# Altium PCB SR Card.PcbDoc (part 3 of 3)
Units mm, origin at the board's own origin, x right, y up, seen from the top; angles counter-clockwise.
Board outline 110.01 x 84.94 mm, 10 copper layers (Top Layer, Layer 2, Layer 3, Layer 4, Layer 5, Layer 6, Layer 7, Layer 8, Layer 9, Bottom Layer), stack 2.452 mm thick; 165 components, 84 nets, 582 pads, 1965 vias.
Unrouted connection lines stored in the file: 24.
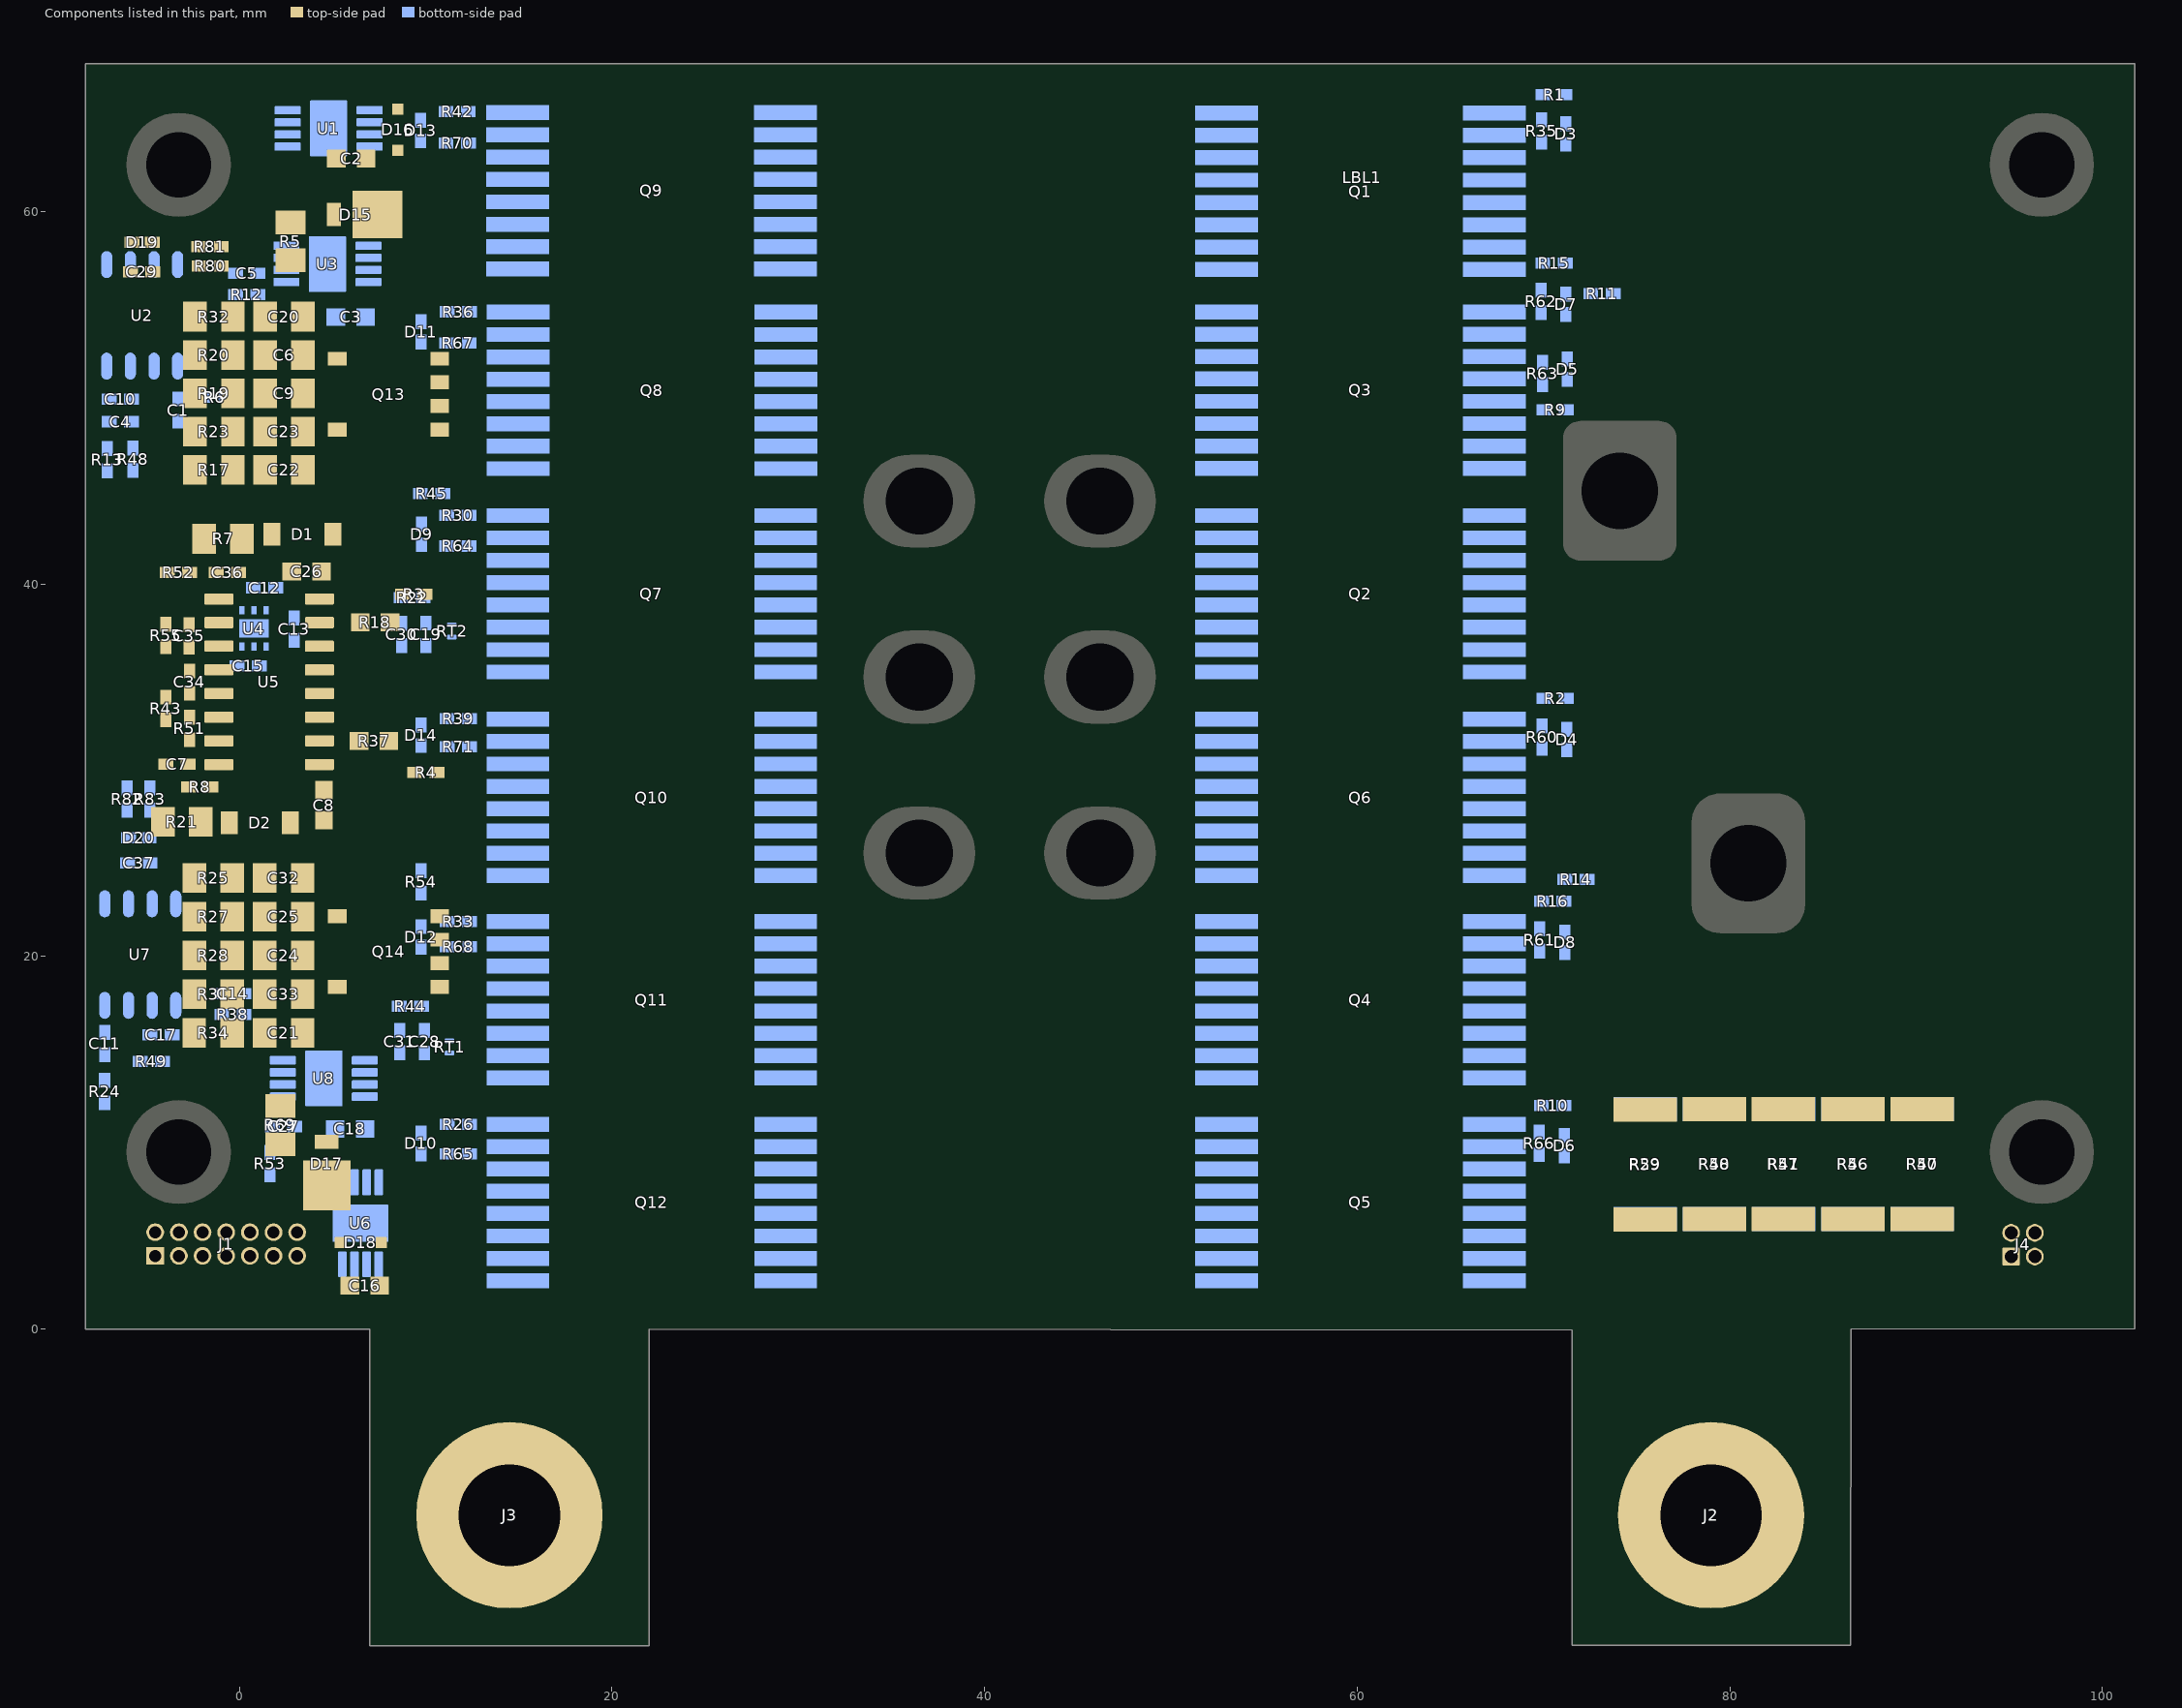
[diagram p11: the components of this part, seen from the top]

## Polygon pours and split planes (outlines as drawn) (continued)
NetC2_1 on Bottom Layer "BOTTOM_LAYER_NONET_P365" (solid, pour order 365): 22 vertices, not listed, extent 1.774,61.651 7.887,63.7
"SR1 LO" on Bottom Layer "BOTTOM_LAYER_SR1_LO_P364" (solid, pour order 364): 6.219,56.632 6.153,56.698 6.153,57.587 6.274,57.708 7.654,57.708 7.805,57.558 7.805,56.764 7.669,56.628 7.409,56.628
DGND on Bottom Layer "BOTTOM_LAYER_DGND_P363" (solid, pour order 363): 29 vertices, not listed, extent -1.053,53.832 7.809,59.908
"SR1 HO" on Bottom Layer "BOTTOM_LAYER_SR1_HO_P353" (solid, pour order 353): 6.297,63.909 6.253,63.953 6.253,64.924 6.33,65.002 7.692,65.002 7.789,64.904 7.789,63.995 7.701,63.908
VSEC+ on Bottom Layer "BOTTOM_LAYER_VSEC+_P352" (solid, pour order 352): 17 vertices, not listed, extent 1.746,62.576 8.446,66.796
DGND on Bottom Layer "Bottom Layer-DGND" (solid, pour order 346): 21 vertices, not listed, extent 7.014,-16.999 21.996,66.742
VBIAS on Bottom Layer "BOTTOM_LAYER_VBIAS_P317" (solid, pour order 317): 93.908,0.927 93.908,7.879 93.095,8.693 71.987,8.693 71.518,6.854 71.518,-16.978 86.463,-16.978 86.463,0.058 86.5,0.022 93.004,0.022
VSR on Bottom Layer "BOTTOM_LAYER_VSR_P308" (solid, remove dead copper, pour order 308): 17 vertices, not listed, extent 60.72,1.857 101.745,67.544
VOUT on Bottom Layer "BOTTOM_LAYER_VOUT_P264" (solid, remove dead copper, pour order 264): 94.2,8.978 97.219,5.96 97.219,1.284 98.086,0.417 100.438,0.417 101.745,1.724 101.745,27.694 100.104,29.336 77.048,29.336 72.036,9.026
VSEC- on Bottom Layer "BOTTOM_LAYER_VSEC-_P239" (solid, pour order 239): 20 vertices, not listed, extent 22.617,1.788 59.33,33.345
VSEC+ on Bottom Layer "BOTTOM_LAYER_VSEC+_P022" (solid, remove dead copper, pour order 22): 19 vertices, not listed, extent 22.583,22.49 59.637,65.946
DGND on Layer 9 "LAYER_9_DGND_P229" (solid, pour order 229): 20 vertices, not listed, extent -8.263,-16.999 101.745,67.936
VSEC- on Layer 9 "LAYER_9_VSEC-_P388" (solid, pour order 388): 23.902,1.693 31.778,1.693 31.778,33.795 23.902,33.795
VSEC+ on Layer 9 "LAYER_9_VSEC+_P311" (solid, pour order 311): 23.888,34.258 31.764,34.258 31.764,66.36 23.888,66.36
VBIAS on Layer 9 "LAYER_9_VBIAS_P341" (solid, pour order 341): 90.97,0.022 93.004,0.022 93.908,0.927 93.908,7.879 93.095,8.693 71.987,8.693 71.518,6.854 71.518,-16.978 86.463,-16.978 86.463,0.058 86.5,0.022
VOUT on Layer 9 "LAYER_9_VOUT_P340" (solid, remove dead copper, pour order 340): 94.136,8.979 94.186,8.979 97.2,5.964 97.2,1.303 98.108,0.395 100.721,0.395 101.745,1.419 101.745,28.007 100.416,29.336 77.048,29.336 72.036,9.026
VSR on Layer 9 "LAYER_9_VSR_P316" (solid, pour order 316): 78.304,31.96 99.913,31.96 99.913,67.043 78.304,67.043
VSEC+ on Layer 9 "LAYER_9_VSEC+_P315" (solid, pour order 315): 57.142,0.357 57.142,66.449 56.645,66.946 49.959,66.946 49.176,66.163 49.266,66.073 49.266,2.767 49.236,2.737 49.266,2.707 49.266,0.598
VSR on Layer 9 "LAYER_9_VSR_P313" (solid, pour order 313): 69.802,0.334 69.802,66.426 69.305,66.924 62.619,66.924 61.836,66.141 61.926,66.05 61.926,2.744 61.896,2.714 61.926,2.684 61.926,0.576
VSEC- on Layer 9 "LAYER_9_VSEC-_P312" (solid, pour order 312): 57.142,0.357 57.142,66.449 56.645,66.946 49.959,66.946 49.176,66.163 49.266,66.073 49.266,2.767 49.236,2.737 49.266,2.707 49.266,0.598
AGND on Layer 2 "LAYER_2_AGND_P344" (solid, remove dead copper, pour order 344): 18 vertices, not listed, extent -8.259,-0.029 8.344,41.938
DGND on Layer 2 "LAYER_2_DGND_P282" (solid, remove dead copper, pour order 282): 20 vertices, not listed, extent -8.263,0.78 21.995,67.359
VBIAS on Layer 2 "LAYER_2_VBIAS_P337" (solid, pour order 337): 93.893,3.56 93.893,7.895 93.095,8.693 71.987,8.693 71.518,6.854 71.518,-16.978 86.463,-16.955 86.463,0.058 86.5,0.022 92.346,0.022 93.893,1.569
VOUT on Layer 2 "LAYER_2_VOUT_P336" (solid, remove dead copper, pour order 336): 94.009,8.979 97.206,5.782 97.206,1.25 98.06,0.395 100.746,0.395 101.745,1.394 101.745,27.898 100.307,29.336 77.048,29.336 72.036,9.026
VSR on Layer 2 "LAYER_2_VSR_P300" (solid, remove dead copper, pour order 300): 20 vertices, not listed, extent 60.72,1.857 101.745,67.544
VSEC- on Layer 2 "LAYER_2_VSEC-_P287" (solid, pour order 287): 34 vertices, not listed, extent 71.708,10.877 75.431,33.607
VSEC+ on Layer 2 "LAYER_2_VSEC+_P286" (solid, pour order 286): 30 vertices, not listed, extent 71.814,49.781 75.316,65.928
DGND on Layer 2 "LAYER_2_DGND_P283" (solid, pour order 283): 7,-17.004 7,-0.008 7.007,-0.001 21.986,-0.001 21.996,-0.01 21.996,-16.998
VSEC+ on Layer 2 "LAYER_2_VSEC+_P255" (solid, pour order 255): 59.382,65.951 59.637,65.695 59.637,2.439 58.987,1.788 23.196,1.788 22.604,2.38 22.604,65.461 23.093,65.951
VSEC- on Layer 2 "LAYER_2_VSEC-_P254" (solid, pour order 254): 40.395,46.429 45.236,41.588 49.521,41.588 51.629,39.48 59.637,39.48 59.637,2.439 58.987,1.788 23.196,1.788 22.604,2.38 22.604,46.429
DGND on Layer 5 "LAYER_5_DGND_P304" (solid, remove dead copper, pour order 304): 6.974,-16.999 22.001,-16.999 22.001,67.581 21.686,67.895 -8.268,67.895 -8.268,1.978 -6.395,0.105 6.974,0.105
VBIAS on Layer 5 "LAYER_5_VBIAS_P331" (solid, pour order 331): 93.908,1.555 93.908,7.879 93.095,8.693 71.987,8.693 71.518,6.854 71.518,-16.978 86.463,-16.978 86.463,0.058 86.5,0.022 92.375,0.022
VOUT on Layer 5 "LAYER_5_VOUT_P330" (solid, remove dead copper, pour order 330): 94.275,8.978 94.275,8.632 97.239,5.668 97.239,1.217 98.06,0.395 100.485,0.395 101.745,1.655 101.745,28.104 100.513,29.336 77.048,29.336 72.036,9.026
VSR on Layer 5 "LAYER_5_VSR_P294" (solid, remove dead copper, pour order 294): 100.822,29.554 101.745,30.477 101.745,66.054 100.255,67.544 60.72,67.544 60.72,1.857 71.315,1.857 71.315,6.854 76.847,29.373 77.05,29.538
VSEC- on Layer 5 "LAYER_5_VSEC-_P259" (solid, pour order 259): 59.386,65.946 59.637,65.695 59.637,2.439 58.987,1.788 23.196,1.788 22.604,2.38 22.604,65.461 23.089,65.946
VSEC+ on Layer 5 "LAYER_5_VSEC+_P258" (solid, pour order 258): 41.846,22.016 36.568,27.294 22.604,27.294 22.604,65.461 23.089,65.946 59.386,65.946 59.637,65.695 59.637,22.016
DGND on Layer 3 "LAYER_3_DGND_P386" (solid, remove dead copper, pour order 386): 6.974,-16.999 22.001,-16.999 22.001,67.581 21.686,67.895 -8.268,67.895 -8.268,1.978 -6.395,0.105 6.974,0.105
"SR1 LO" on Layer 3 "LAYER_3_SR1_LO_P280" (solid, pour order 280): 50 vertices, not listed, extent 6.486,42.661 11.667,65.156
VBIAS on Layer 3 "LAYER_3_VBIAS_P351" (solid, pour order 351): 71.518,2.551 75.738,6.77 75.738,8.693 93.095,8.693 93.894,7.894 93.894,1.57 92.346,0.022 86.5,0.022 86.463,0.058 86.463,-16.955 71.518,-16.978
VOUT on Layer 3 "LAYER_3_VOUT_P350" (solid, remove dead copper, pour order 350): 95.16,9.026 95.16,7.829 97.242,5.748 97.242,1.214 98.06,0.395 100.439,0.395 101.414,1.369 101.414,28.204 100.281,29.336 77.048,29.336 75.738,24.027 75.738,9.026
VSR on Layer 3 "LAYER_3_NONET_P349" (solid, pour order 349): 24 vertices, not listed, extent 60.72,2.048 101.745,67.544
"SR1 HO" on Layer 3 "LAYER_3_SR1_HO_P348" (solid, pour order 348): 32 vertices, not listed, extent 70.813,50.099 75.316,65.988
"SR2 HO" on Layer 3 "LAYER_3_SR2_HO_P347" (solid, pour order 347): 34 vertices, not listed, extent 70.725,10.594 75.431,33.673
"SR2 LO" on Layer 3 "LAYER_3_SR2_LO_P281" (solid, pour order 281): 56 vertices, not listed, extent 6.35,9.871 12.241,32.594
VSEC- on Layer 3 "LAYER_3_VSEC-_P261" (solid, pour order 261): 59.386,65.946 59.637,65.695 59.637,2.439 58.987,1.788 23.196,1.788 22.604,2.38 22.604,65.461 23.089,65.946
VSEC+ on Layer 3 "LAYER_3_VSEC+_P260" (solid, pour order 260): 41.846,22.016 36.568,27.294 22.604,27.294 22.604,65.461 23.089,65.946 59.386,65.946 59.637,65.695 59.637,22.016

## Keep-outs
Keep-Out Layer:
  lines w0.254: 6.669,0.025 -8.29,0 -8.293,67.942 101.75,67.94 101.75,0 86.886,-0.02 ; 22.349,-0.011 71.206,-0.072
  text ".Layer_Name" at 4.656,-21.806 h0.6

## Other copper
Top Layer:
  rectangle net NetD1_2: -0.337,41.958 2.132,43.262
  rectangle net NetD2_2: -2.544,26.528 -0.075,27.833
  text ".Layer_Name" at 4.656,-21.806 h0.6
Layer 3:
  pour cut-out: 1.331,37.219 cw(c1.331,37.848) 0.702,37.848 cw(c1.331,37.848) 1.331,38.476 cw(c1.331,37.848) 1.959,37.848 cw(c1.331,37.848)
  pour cut-out: 0.702,37.282 cw(c0.702,37.91) 0.074,37.91 cw(c0.702,37.91) 0.702,38.539 cw(c0.702,37.91) 1.331,37.91 cw(c0.702,37.91)
  pour cut-out: 1.331,37.219 cw(c1.331,37.848) 0.702,37.848 cw(c1.331,37.848) 1.331,38.476 cw(c1.331,37.848) 1.959,37.848 cw(c1.331,37.848)
  pour cut-out: 8.274,34.085 cw(c8.274,34.713) 7.646,34.713 cw(c8.274,34.713) 8.274,35.341 cw(c8.274,34.713) 8.903,34.713 cw(c8.274,34.713)
  region net VSEC+: 3.932,65.77 3.932,63.171 4.119,62.984 5.536,62.984 5.627,63.076 5.627,65.821 5.448,66 4.163,66
  region net VSEC-: 6.314,4.847 6.172,4.989 6.172,6.314 6.345,6.488 7.907,6.488 8.005,6.389 8.005,4.954 7.899,4.847
  region net DGND: -2.595,17.497 -2.415,17.676 -1.901,17.676 -1.746,17.522 -1.746,15.194 -1.952,14.988 -2.423,14.988 -2.595,15.16
  region net DGND: -2.443,19.617 -1.92,19.617 -1.738,19.8 -1.738,24.932 -1.9,25.094 -2.369,25.094 -2.591,24.872 -2.591,19.765
  region net DGND: -3.666,47.665 -3.448,47.883 -2.889,47.883 -2.571,48.201 -2.571,48.597 -2.335,48.834 -1.861,48.834 -1.707,48.679 -1.707,46.339 -1.969,46.077 -3.419,46.077 -3.666,46.324
  region net DGND: -3.427,52.583 -3.601,52.757 -3.601,54.163 -3.341,54.422 -1.957,54.422 -1.729,54.195 -1.729,50.985 -1.95,50.764 -2.321,50.764 -2.561,51.004 -2.561,52.284 -2.86,52.583
  region net NetC6_2: -0.645,54.608 -0.463,54.789 0.743,54.789 1.055,54.477 1.055,53.111 1.71,52.456 1.71,46.048 1.493,45.831 -0.47,45.831 -0.645,46.006
  region net NetC21_2: 1.464,19.681 -0.499,19.681 -0.692,19.874 -0.692,24.405 -0.479,24.618 1.457,24.618 1.681,24.394 1.681,19.898
  region net NetC6_1: 7.098,48.584 4.996,48.584 4.638,48.941 4.638,51.473 5.08,51.914 7.039,51.914 7.479,51.474 7.479,48.965
  region net NetC21_1: 5.395,18.683 5.556,18.844 5.556,22.255 6.064,22.763 7.132,22.763 7.498,23.093 7.498,23.667 7.118,24.047 5.134,24.047 4.658,23.571 4.658,18.912 4.886,18.683
  pour cut-out: -2.49,50.375 -2.955,50.84 -2.955,51.872 -3.195,52.112 -3.734,52.112 -4.011,52.378 -4.011,54.461 -3.568,54.903 -1.781,54.903 -1.417,54.539 -1.417,50.609 -1.65,50.375
  pour cut-out: -3.022,19.579 -2.63,19.187 -1.74,19.187 -1.345,19.582 -1.345,25.237 -1.705,25.598 -2.678,25.598 -3.022,25.254
  pour cut-out: -3.022,14.992 -2.464,14.434 -1.822,14.434 -1.345,14.911 -1.345,17.813 -1.705,18.173 -2.678,18.173 -3.022,17.829
  pour cut-out: -4.011,45.921 -3.765,45.675 -1.682,45.675 -1.417,45.929 -1.417,48.971 -1.68,49.233 -2.569,49.233 -2.905,48.897 -2.905,48.418 -3.154,48.17 -3.767,48.17 -4.012,47.925 -4.011,47.792
Layer 5:
  pour cut-out: -4.422,38.529 cw(c-4.422,39.157) -5.05,39.157 cw(c-4.422,39.157) -4.422,39.785 cw(c-4.422,39.157) -3.794,39.157 cw(c-4.422,39.157)
  pour cut-out: 8.274,34.085 cw(c8.274,34.713) 7.646,34.713 cw(c8.274,34.713) 8.274,35.341 cw(c8.274,34.713) 8.903,34.713 cw(c8.274,34.713)
  pour cut-out: 0.702,37.219 cw(c0.702,37.848) 0.074,37.848 cw(c0.702,37.848) 0.702,38.476 cw(c0.702,37.848) 1.331,37.848 cw(c0.702,37.848)
  pour cut-out: 1.331,37.219 cw(c1.331,37.848) 0.702,37.848 cw(c1.331,37.848) 1.331,38.476 cw(c1.331,37.848) 1.959,37.848 cw(c1.331,37.848)
  pour cut-out: -2.752,3.103 -2.618,2.968 -1.38,2.968 -1.21,3.138 -1.21,5.784 -1.385,5.958 -2.559,5.958 -2.752,5.765
  region net DGND: -3.427,52.583 -3.601,52.757 -3.601,54.163 -3.341,54.422 -1.957,54.422 -1.729,54.195 -1.729,50.985 -1.95,50.764 -2.321,50.764 -2.561,51.004 -2.561,52.284 -2.86,52.583
  region net DGND: -3.666,47.665 -3.448,47.883 -2.889,47.883 -2.571,48.201 -2.571,48.597 -2.335,48.834 -1.861,48.834 -1.707,48.679 -1.707,46.339 -1.969,46.077 -3.419,46.077 -3.666,46.324
  region net DGND: -2.443,19.617 -1.92,19.617 -1.738,19.8 -1.738,24.932 -1.9,25.094 -2.369,25.094 -2.591,24.872 -2.591,19.765
  region net DGND: -2.595,17.497 -2.415,17.676 -1.901,17.676 -1.746,17.522 -1.746,15.194 -1.952,14.988 -2.423,14.988 -2.595,15.16
  region net VSEC-: 6.314,4.847 6.172,4.989 6.172,6.314 6.345,6.488 7.907,6.488 8.005,6.389 8.005,4.954 7.899,4.847
  region net VSEC+: 3.932,65.77 3.932,63.171 4.119,62.984 5.536,62.984 5.627,63.076 5.627,65.821 5.448,66 4.163,66
  region net NetC6_2: -0.645,54.608 -0.463,54.789 0.743,54.789 1.055,54.477 1.055,53.111 1.71,52.456 1.71,46.048 1.493,45.831 -0.47,45.831 -0.645,46.006
  region net NetC21_2: 1.464,19.681 -0.499,19.681 -0.692,19.874 -0.692,24.405 -0.479,24.618 1.457,24.618 1.681,24.394 1.681,19.898
  region net NetC21_1: 7.117,18.554 5.015,18.554 4.658,18.912 4.658,23.571 5.134,24.047 7.058,24.047 7.498,23.607 7.498,18.935
  region net NetC6_1: 7.098,48.584 4.996,48.584 4.638,48.941 4.638,51.473 5.08,51.914 7.039,51.914 7.479,51.474 7.479,48.965
  pour cut-out: -2.49,50.375 -2.955,50.84 -2.955,51.872 -3.195,52.112 -3.734,52.112 -4.011,52.378 -4.011,54.461 -3.568,54.903 -1.781,54.903 -1.417,54.539 -1.417,50.609 -1.65,50.375
  pour cut-out: -3.022,19.579 -2.63,19.187 -1.74,19.187 -1.345,19.582 -1.345,25.237 -1.705,25.598 -2.678,25.598 -3.022,25.254
  pour cut-out: -3.022,14.992 -2.464,14.434 -1.822,14.434 -1.345,14.911 -1.345,17.813 -1.705,18.173 -2.678,18.173 -3.022,17.829
  pour cut-out: -4.011,45.921 -3.765,45.675 -1.682,45.675 -1.417,45.929 -1.417,48.971 -1.68,49.233 -2.569,49.233 -2.905,48.897 -2.905,48.294 -3.03,48.17 -3.767,48.17 -4.012,47.925 -4.011,47.792
Layer 6:
  pour cut-out: -4.422,38.529 cw(c-4.422,39.157) -5.05,39.157 cw(c-4.422,39.157) -4.422,39.785 cw(c-4.422,39.157) -3.794,39.157 cw(c-4.422,39.157)
  pour cut-out: 0.707,37.214 cw(c0.707,37.843) 0.079,37.843 cw(c0.707,37.843) 0.707,38.471 cw(c0.707,37.843) 1.336,37.843 cw(c0.707,37.843)
  pour cut-out: 1.331,37.219 cw(c1.331,37.848) 0.702,37.848 cw(c1.331,37.848) 1.331,38.476 cw(c1.331,37.848) 1.959,37.848 cw(c1.331,37.848)
  pour cut-out: 8.274,34.085 cw(c8.274,34.713) 7.646,34.713 cw(c8.274,34.713) 8.274,35.341 cw(c8.274,34.713) 8.903,34.713 cw(c8.274,34.713)
  pour cut-out: -2.752,3.05 -1.21,3.05 -1.21,5.784 -1.385,5.958 -2.559,5.958 -2.752,5.765
  region net DGND: -3.427,52.583 -3.601,52.757 -3.601,54.163 -3.341,54.422 -1.957,54.422 -1.729,54.195 -1.729,50.985 -1.95,50.764 -2.321,50.764 -2.561,51.004 -2.561,52.284 -2.86,52.583
  region net DGND: -3.666,47.665 -3.448,47.883 -2.889,47.883 -2.571,48.201 -2.571,48.597 -2.335,48.834 -1.861,48.834 -1.707,48.679 -1.707,46.339 -1.969,46.077 -3.419,46.077 -3.666,46.324
  region net DGND: -2.443,19.617 -1.92,19.617 -1.738,19.8 -1.738,24.932 -1.9,25.094 -2.369,25.094 -2.591,24.872 -2.591,19.765
  region net DGND: -2.595,17.497 -2.415,17.676 -1.901,17.676 -1.746,17.522 -1.746,15.194 -1.952,14.988 -2.423,14.988 -2.595,15.16
  region net VSEC-: 6.314,4.847 6.172,4.989 6.172,6.314 6.345,6.488 7.907,6.488 8.005,6.389 8.005,4.954 7.899,4.847
  region net VSEC+: 3.932,65.77 3.932,63.171 4.119,62.984 5.536,62.984 5.627,63.076 5.627,65.821 5.448,66 4.163,66
  region net NetC6_2: -0.645,54.608 -0.463,54.789 0.743,54.789 1.055,54.477 1.055,53.111 1.71,52.456 1.71,46.048 1.493,45.831 -0.47,45.831 -0.645,46.006
  region net NetC21_2: 1.464,19.681 -0.499,19.681 -0.692,19.874 -0.692,24.405 -0.479,24.618 1.457,24.618 1.681,24.394 1.681,19.898
  region net NetC21_1: 7.117,18.554 5.015,18.554 4.658,18.912 4.658,23.571 5.134,24.047 7.058,24.047 7.498,23.607 7.498,18.935
  region net NetC6_1: 7.098,48.584 4.996,48.584 4.638,48.941 4.638,51.473 5.08,51.914 7.039,51.914 7.479,51.474 7.479,48.965
  pour cut-out: -2.49,50.375 -2.955,50.84 -2.955,51.872 -3.195,52.112 -3.734,52.112 -4.011,52.378 -4.011,54.461 -3.568,54.903 -1.781,54.903 -1.417,54.539 -1.417,50.609 -1.65,50.375
  pour cut-out: -3.022,19.579 -2.63,19.187 -1.74,19.187 -1.345,19.582 -1.345,25.237 -1.705,25.598 -2.678,25.598 -3.022,25.254
  pour cut-out: -3.022,14.992 -2.464,14.434 -1.822,14.434 -1.345,14.911 -1.345,17.813 -1.705,18.173 -2.678,18.173 -3.022,17.829
  pour cut-out: -4.011,45.921 -3.765,45.675 -1.682,45.675 -1.417,45.929 -1.417,48.971 -1.68,49.233 -2.569,49.233 -2.905,48.897 -2.905,48.294 -3.03,48.17 -3.767,48.17 -4.012,47.925 -4.011,47.792
Layer 8:
  pour cut-out: 8.274,34.085 cw(c8.274,34.713) 7.646,34.713 cw(c8.274,34.713) 8.274,35.341 cw(c8.274,34.713) 8.903,34.713 cw(c8.274,34.713)
  pour cut-out: 1.331,37.219 cw(c1.331,37.848) 0.702,37.848 cw(c1.331,37.848) 1.331,38.476 cw(c1.331,37.848) 1.959,37.848 cw(c1.331,37.848)
  pour cut-out: 0.707,37.214 cw(c0.707,37.843) 0.079,37.843 cw(c0.707,37.843) 0.707,38.471 cw(c0.707,37.843) 1.336,37.843 cw(c0.707,37.843)
  pour cut-out: -4.422,38.529 cw(c-4.422,39.157) -5.05,39.157 cw(c-4.422,39.157) -4.422,39.785 cw(c-4.422,39.157) -3.794,39.157 cw(c-4.422,39.157)
  pour cut-out: -1.21,3.009 -2.752,3.009 -2.752,5.765 -2.559,5.958 -1.385,5.958 -1.21,5.784
  region net DGND: -3.427,52.583 -3.601,52.757 -3.601,54.163 -3.341,54.422 -1.957,54.422 -1.729,54.195 -1.729,50.985 -1.95,50.764 -2.321,50.764 -2.561,51.004 -2.561,52.284 -2.86,52.583
  region net DGND: -3.666,47.665 -3.448,47.883 -2.889,47.883 -2.571,48.201 -2.571,48.597 -2.335,48.834 -1.861,48.834 -1.707,48.679 -1.707,46.339 -1.969,46.077 -3.419,46.077 -3.666,46.324
  region net DGND: -2.443,19.617 -1.92,19.617 -1.738,19.8 -1.738,24.932 -1.9,25.094 -2.369,25.094 -2.591,24.872 -2.591,19.765
  region net DGND: -2.595,17.497 -2.415,17.676 -1.901,17.676 -1.746,17.522 -1.746,15.194 -1.952,14.988 -2.423,14.988 -2.595,15.16
  region net VSEC-: 6.314,4.847 6.172,4.989 6.172,6.314 6.345,6.488 7.907,6.488 8.005,6.389 8.005,4.954 7.899,4.847
  region net VSEC+: 3.932,65.77 3.932,63.171 4.119,62.984 5.536,62.984 5.627,63.076 5.627,65.821 5.448,66 4.163,66
  region net NetC6_2: -0.645,54.608 -0.463,54.789 0.743,54.789 1.055,54.477 1.055,53.111 1.71,52.456 1.71,46.048 1.493,45.831 -0.47,45.831 -0.645,46.006
  region net NetC21_2: 1.464,19.681 -0.499,19.681 -0.692,19.874 -0.692,24.405 -0.479,24.618 1.457,24.618 1.681,24.394 1.681,19.898
  region net NetC21_1: 7.117,18.554 5.015,18.554 4.658,18.912 4.658,23.571 5.134,24.047 7.058,24.047 7.498,23.607 7.498,18.935
  region net NetC6_1: 7.098,48.584 4.996,48.584 4.638,48.941 4.638,51.473 5.08,51.914 7.039,51.914 7.479,51.474 7.479,48.965
  pour cut-out: -2.49,50.375 -2.955,50.84 -2.955,51.872 -3.195,52.112 -3.734,52.112 -4.011,52.378 -4.011,54.461 -3.568,54.903 -1.781,54.903 -1.417,54.539 -1.417,50.609 -1.65,50.375
  pour cut-out: -3.022,19.579 -2.63,19.187 -1.74,19.187 -1.345,19.582 -1.345,25.237 -1.705,25.598 -2.678,25.598 -3.022,25.254
  pour cut-out: -3.022,14.992 -2.464,14.434 -1.822,14.434 -1.345,14.911 -1.345,17.813 -1.705,18.173 -2.678,18.173 -3.022,17.829
  pour cut-out: -4.011,45.921 -3.765,45.675 -1.682,45.675 -1.417,45.929 -1.417,48.971 -1.68,49.233 -2.569,49.233 -2.905,48.897 -2.905,48.294 -3.03,48.17 -3.767,48.17 -4.012,47.925 -4.011,47.792
Layer 9:
  region net DGND: -3.427,52.583 -3.601,52.757 -3.601,54.163 -3.341,54.422 -1.957,54.422 -1.729,54.195 -1.729,50.985 -1.95,50.764 -2.321,50.764 -2.561,51.004 -2.561,52.284 -2.86,52.583
  region net DGND: -3.666,47.665 -3.448,47.883 -2.889,47.883 -2.571,48.201 -2.571,48.597 -2.335,48.834 -1.861,48.834 -1.707,48.679 -1.707,46.339 -1.969,46.077 -3.419,46.077 -3.666,46.324
  region net DGND: -2.443,19.617 -1.92,19.617 -1.738,19.8 -1.738,24.932 -1.9,25.094 -2.369,25.094 -2.591,24.872 -2.591,19.765
  region net DGND: -2.595,17.497 -2.415,17.676 -1.901,17.676 -1.746,17.522 -1.746,15.194 -1.952,14.988 -2.423,14.988 -2.595,15.16
  region net VSEC-: 6.314,4.847 6.172,4.989 6.172,6.314 6.345,6.488 7.907,6.488 8.005,6.389 8.005,4.954 7.899,4.847
  region net VSEC+: 3.932,65.77 3.932,63.171 4.119,62.984 5.536,62.984 5.627,63.076 5.627,65.821 5.448,66 4.163,66
  region net NetC21_2: 1.464,19.681 -0.499,19.681 -0.692,19.874 -0.692,24.405 -0.479,24.618 1.457,24.618 1.681,24.394 1.681,19.898
  region net NetC6_2: -0.645,54.608 -0.463,54.789 0.743,54.789 1.055,54.477 1.055,53.111 1.71,52.456 1.71,46.048 1.493,45.831 -0.47,45.831 -0.645,46.006
  region net NetC21_1: 7.117,18.554 5.015,18.554 4.658,18.912 4.658,23.571 5.134,24.047 7.058,24.047 7.498,23.607 7.498,18.935
  region net NetC6_1: 7.098,48.584 4.996,48.584 4.638,48.941 4.638,51.473 5.08,51.914 7.039,51.914 7.479,51.474 7.479,48.965
  pour cut-out: -4.011,45.921 -3.765,45.675 -1.682,45.675 -1.417,45.929 -1.417,48.971 -1.68,49.233 -2.569,49.233 -2.905,48.897 -2.905,48.294 -3.03,48.17 -3.767,48.17 -4.012,47.925 -4.011,47.792
  pour cut-out: -3.022,14.992 -2.464,14.434 -1.822,14.434 -1.345,14.911 -1.345,17.813 -1.705,18.173 -2.678,18.173 -3.022,17.829
  pour cut-out: -3.022,19.579 -2.63,19.187 -1.74,19.187 -1.345,19.582 -1.345,25.237 -1.705,25.598 -2.678,25.598 -3.022,25.254
  pour cut-out: -2.49,50.375 -2.955,50.84 -2.955,51.872 -3.195,52.112 -3.734,52.112 -4.011,52.378 -4.011,54.461 -3.568,54.903 -1.781,54.903 -1.417,54.539 -1.417,50.609 -1.65,50.375
Layer 4:
  pour cut-out: -4.422,38.529 cw(c-4.422,39.157) -5.05,39.157 cw(c-4.422,39.157) -4.422,39.785 cw(c-4.422,39.157) -3.794,39.157 cw(c-4.422,39.157)
  pour cut-out: 0.707,37.214 cw(c0.707,37.843) 0.079,37.843 cw(c0.707,37.843) 0.707,38.471 cw(c0.707,37.843) 1.336,37.843 cw(c0.707,37.843)
  pour cut-out: 1.331,37.219 cw(c1.331,37.848) 0.702,37.848 cw(c1.331,37.848) 1.331,38.476 cw(c1.331,37.848) 1.959,37.848 cw(c1.331,37.848)
  pour cut-out: 8.274,34.085 cw(c8.274,34.713) 7.646,34.713 cw(c8.274,34.713) 8.274,35.341 cw(c8.274,34.713) 8.903,34.713 cw(c8.274,34.713)
  pour cut-out: -2.562,3.057 -1.461,3.057 -1.292,3.226 -1.292,5.866 -1.364,5.937 -2.58,5.937 -2.641,5.877 -2.641,3.136
  region net DGND: -3.427,52.583 -3.601,52.757 -3.601,54.163 -3.341,54.422 -1.957,54.422 -1.729,54.195 -1.729,50.985 -1.95,50.764 -2.321,50.764 -2.561,51.004 -2.561,52.284 -2.86,52.583
  region net DGND: -3.666,47.665 -3.448,47.883 -2.889,47.883 -2.571,48.201 -2.571,48.597 -2.335,48.834 -1.861,48.834 -1.707,48.679 -1.707,46.339 -1.969,46.077 -3.419,46.077 -3.666,46.324
  region net DGND: -2.443,19.617 -1.92,19.617 -1.738,19.8 -1.738,24.932 -1.9,25.094 -2.369,25.094 -2.591,24.872 -2.591,19.765
  region net DGND: -2.595,17.497 -2.415,17.676 -1.901,17.676 -1.746,17.522 -1.746,15.194 -1.952,14.988 -2.423,14.988 -2.595,15.16
  region net VSEC-: 6.314,4.847 6.172,4.989 6.172,6.314 6.345,6.488 7.907,6.488 8.005,6.389 8.005,4.954 7.899,4.847
  region net VSEC+: 3.932,65.77 3.932,63.171 4.119,62.984 5.536,62.984 5.627,63.076 5.627,65.821 5.448,66 4.163,66
  region net NetC6_2: -0.645,54.608 -0.463,54.789 0.743,54.789 1.055,54.477 1.055,53.111 1.71,52.456 1.71,46.048 1.493,45.831 -0.47,45.831 -0.645,46.006
  region net NetC21_2: 1.464,19.681 -0.499,19.681 -0.692,19.874 -0.692,24.405 -0.479,24.618 1.457,24.618 1.681,24.394 1.681,19.898
  region net NetC21_1: 5.395,18.683 5.556,18.844 5.556,22.255 6.064,22.763 7.132,22.763 7.498,23.093 7.498,23.667 7.118,24.047 5.134,24.047 4.658,23.571 4.658,18.912 4.886,18.683
  region net NetC6_1: 7.098,48.584 4.996,48.584 4.638,48.941 4.638,51.473 5.08,51.914 7.039,51.914 7.479,51.474 7.479,48.965
  pour cut-out: -2.49,50.375 -2.955,50.84 -2.955,51.872 -3.195,52.112 -3.734,52.112 -4.011,52.378 -4.011,54.461 -3.568,54.903 -1.781,54.903 -1.417,54.539 -1.417,50.609 -1.65,50.375
  pour cut-out: -3.022,19.579 -2.63,19.187 -1.74,19.187 -1.345,19.582 -1.345,25.237 -1.705,25.598 -2.678,25.598 -3.022,25.254
  pour cut-out: -3.022,14.992 -2.464,14.434 -1.822,14.434 -1.345,14.911 -1.345,17.813 -1.705,18.173 -2.678,18.173 -3.022,17.829
  pour cut-out: -4.011,45.921 -3.765,45.675 -1.682,45.675 -1.417,45.929 -1.417,48.971 -1.68,49.233 -2.569,49.233 -2.905,48.897 -2.905,48.294 -3.03,48.17 -3.767,48.17 -4.012,47.925 -4.011,47.792
Layer 7:
  pour cut-out: 8.274,34.085 cw(c8.274,34.713) 7.646,34.713 cw(c8.274,34.713) 8.274,35.341 cw(c8.274,34.713) 8.903,34.713 cw(c8.274,34.713)
  pour cut-out: 0.707,37.214 cw(c0.707,37.843) 0.079,37.843 cw(c0.707,37.843) 0.707,38.471 cw(c0.707,37.843) 1.336,37.843 cw(c0.707,37.843)
  pour cut-out: 1.331,37.219 cw(c1.331,37.848) 0.702,37.848 cw(c1.331,37.848) 1.331,38.476 cw(c1.331,37.848) 1.959,37.848 cw(c1.331,37.848)
  pour cut-out: -4.422,38.529 cw(c-4.422,39.157) -5.05,39.157 cw(c-4.422,39.157) -4.422,39.785 cw(c-4.422,39.157) -3.794,39.157 cw(c-4.422,39.157)
  pour cut-out: -1.21,3.019 -2.752,3.019 -2.752,5.765 -2.559,5.958 -1.385,5.958 -1.21,5.784
  region net DGND: -3.427,52.583 -3.601,52.757 -3.601,54.163 -3.341,54.422 -1.957,54.422 -1.729,54.195 -1.729,50.985 -1.95,50.764 -2.321,50.764 -2.561,51.004 -2.561,52.284 -2.86,52.583
  region net DGND: -3.666,47.665 -3.448,47.883 -2.889,47.883 -2.571,48.201 -2.571,48.597 -2.335,48.834 -1.861,48.834 -1.707,48.679 -1.707,46.339 -1.969,46.077 -3.419,46.077 -3.666,46.324
  region net DGND: -2.443,19.617 -1.92,19.617 -1.738,19.8 -1.738,24.932 -1.9,25.094 -2.369,25.094 -2.591,24.872 -2.591,19.765
  region net DGND: -2.595,17.497 -2.415,17.676 -1.901,17.676 -1.746,17.522 -1.746,15.194 -1.952,14.988 -2.423,14.988 -2.595,15.16
  region net VSEC-: 6.314,4.847 6.172,4.989 6.172,6.314 6.345,6.488 7.907,6.488 8.005,6.389 8.005,4.954 7.899,4.847
  region net VSEC+: 3.932,65.77 3.932,63.171 4.119,62.984 5.536,62.984 5.627,63.076 5.627,65.821 5.448,66 4.163,66
  region net NetC6_2: -0.645,54.608 -0.463,54.789 0.743,54.789 1.055,54.477 1.055,53.111 1.71,52.456 1.71,46.048 1.493,45.831 -0.47,45.831 -0.645,46.006
  region net NetC21_2: 1.464,19.681 -0.499,19.681 -0.692,19.874 -0.692,24.405 -0.479,24.618 1.457,24.618 1.681,24.394 1.681,19.898
  region net NetC21_1: 7.117,18.554 5.015,18.554 4.658,18.912 4.658,23.571 5.134,24.047 7.058,24.047 7.498,23.607 7.498,18.935
  region net NetC6_1: 7.098,48.584 4.996,48.584 4.638,48.941 4.638,51.473 5.08,51.914 7.039,51.914 7.479,51.474 7.479,48.965
  pour cut-out: -2.49,50.375 -2.955,50.84 -2.955,51.872 -3.195,52.112 -3.734,52.112 -4.011,52.378 -4.011,54.461 -3.568,54.903 -1.781,54.903 -1.417,54.539 -1.417,50.609 -1.65,50.375
  pour cut-out: -3.022,19.579 -2.63,19.187 -1.74,19.187 -1.345,19.582 -1.345,25.237 -1.705,25.598 -2.678,25.598 -3.022,25.254
  pour cut-out: -3.022,14.992 -2.464,14.434 -1.822,14.434 -1.345,14.911 -1.345,17.813 -1.705,18.173 -2.678,18.173 -3.022,17.829
  pour cut-out: -4.011,45.921 -3.765,45.675 -1.682,45.675 -1.417,45.929 -1.417,48.971 -1.68,49.233 -2.569,49.233 -2.905,48.897 -2.905,48.294 -3.03,48.17 -3.767,48.17 -4.012,47.925 -4.011,47.792
Bottom Layer:
  region net DGND: -2.595,17.497 -2.415,17.676 -1.901,17.676 -1.746,17.522 -1.746,15.194 -1.952,14.988 -2.423,14.988 -2.595,15.16
  region net DGND: -2.443,19.617 -1.92,19.617 -1.738,19.8 -1.738,24.932 -1.9,25.094 -2.369,25.094 -2.591,24.872 -2.591,19.765
  region net NetC6_2: -0.645,51.152 0.475,50.032 1.523,50.032 1.724,50.233 1.71,50.242 1.71,52.456 1.055,53.111 1.055,54.477 0.743,54.789 -0.463,54.789 -0.645,54.608
  region net NetC6_2: -0.645,48.416 -0.474,48.586 1.542,48.586 1.71,48.421 1.71,46.048 1.493,45.831 -0.47,45.831 -0.645,46.006
  region net NetC21_2: 1.464,19.681 -0.499,19.681 -0.692,19.874 -0.692,24.405 -0.479,24.618 1.457,24.618 1.681,24.394 1.681,19.898
  region net NetC6_1: 7.098,48.584 4.996,48.584 4.638,48.941 4.638,51.473 5.08,51.914 7.039,51.914 7.479,51.474 7.479,48.965
  region net NetC21_1: 7.117,18.554 5.015,18.554 4.658,18.912 4.658,23.571 5.134,24.047 7.058,24.047 7.498,23.607 7.498,18.935
  region net 12V: 2.296,11.556 3.009,12.27 3.009,12.526 2.84,12.696 1.647,12.696 1.469,12.517 1.469,11.655 1.567,11.556
  region net "SR2 HO": 6.847,2.782 6.122,2.782 6.005,2.898 6.005,4.068 6.098,4.161 6.916,4.161 6.971,4.106 6.971,2.906
  region net "SR2 LO": 6.095,12.953 6.056,12.992 6.056,13.844 6.172,13.96 7.36,13.96 7.415,13.904 7.415,13.079 7.286,12.95
  text ".Layer_Name" at 4.656,-21.806 h0.6

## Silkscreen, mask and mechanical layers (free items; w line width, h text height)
Top Overlay:
  lines w0.254: 16.3,14.8 16.3,54.4 65.3,54.4 65.3,14.8 16.3,14.8 ; 67.3,14.8 67.3,54.4 92.3,54.4 92.3,14.8 67.3,14.8
  text "PMP41147A" at 34.81,63.158 h1.52
  text "SR Card" at 34.877,59.746 h1.52
  text ".Layer_Name" at 4.656,-21.806 h0.6
Bottom Overlay:
  text ".Layer_Name" at 4.656,-21.806 h0.6
Top Paste:
  text ".Layer_Name" at 4.656,-21.806 h0.6
Bottom Paste:
  text ".Layer_Name" at 4.656,-21.806 h0.6
Top Solder:
  rectangle: 85.436,15.588 91.337,29.16
  rectangle: 93.266,15.501 100.808,29.073
  rectangle: 93.301,30.332 100.843,53.298
  rectangle: 78.592,30.559 91.459,53.524
  text ".Layer_Name" at 4.656,-21.806 h0.6
  text ".Layer_Name" at 4.656,-21.806 h0.6
Bottom Solder:
  rectangle: 77.968,39.609 92.374,67.28
  rectangle: 85.436,14.366 100.232,28.813
  rectangle: 78.016,30.995 100.319,58.667
  text ".Layer_Name" at 4.656,-21.806 h0.6
Drill Guide:
  text ".Layer_Name" at 4.656,-21.806 h0.6
M1 Board Outline:
  the board outline again, w0.254
  text ".Layer_Name" at 4.656,-21.806 h0.6
M2 Board Dimensions:
  circle w0.254: c96,5 r1.75
  circle w0.254: c96,35 r1.75
  circle w0.254: c9,35 r1.75
  circle w0.254: c9,5 r1.75
  text ".Layer_Name" at 4.656,-21.806 h0.6
M3 3D STEP Top:
  text ".Layer_Name" at 4.656,-21.806 h0.6
M4 3D STEP Bottom:
  text ".Layer_Name" at 4.656,-21.806 h0.6
Top M5 Assembly Top/M6 Assembly Bottom:
  lines w0.254: -17.417,-23.626 150.223,-23.626 ; -17.417,-18.462 150.274,-18.462 ; -17.417,-13.297 -17.417,-28.791 84.31,-28.791 150.274,-28.791 150.274,-13.297 -17.404,-13.297 -17.404,-28.791 22.614,-28.791 ; 45.194,-28.791 45.194,-13.297 ; 77.376,-18.462 77.376,-13.297 ; 98.712,-18.462 98.712,-13.297 ; 114.511,-28.956 114.511,-23.804
  text "PCB VIEWED FROM TOP SIDE" at -15.804,-16.654 h0.6
  text "BOARD #:" at 47.099,-16.654 h0.6
  text ".PRJ_Number" at 60.955,-16.654 h0.6
  text "REV:" at 82.405,-16.654 h0.6
  text ".PCB_Rev" at 89.809,-16.654 h0.6
  text "SVN REV:" at 103.69,-16.654 h0.6
  text ".VersionControl_RevNumber" at 116.543,-16.654 h0.6
  text "TID #:" at 47.099,-21.819 h0.6
  text ".TID" at 60.955,-21.819 h0.6
  text "PLOT NAME =" at -15.804,-27.034 h0.6
  text ".plot_File_Name" at 4.656,-27.034 h0.6
  text "GENERATED    :" at 47.15,-27.034 h0.6
  text ".Print_Date" at 69.235,-27.034 h0.6
  text ".Print_Time" at 87.752,-27.034 h0.6
  text "TEXAS INSTRUMENTS" at 119.87,-27.034 h0.6
Bottom M5 Assembly Top/M6 Assembly Bottom:
  lines w0.254: -17.43,-18.474 150.261,-18.474 ; -17.379,-23.639 150.261,-23.639 ; 18.334,-28.969 18.334,-23.817 ; 34.132,-18.474 34.132,-13.31 ; 55.468,-18.474 55.468,-13.31 ; 87.65,-28.804 87.65,-13.31 ; 110.231,-28.804 150.249,-28.804 150.249,-13.31 -17.43,-13.31 -17.43,-28.804 48.534,-28.804 150.261,-28.804 150.261,-13.31
  text "COMPONENTS MARKED 'DNP' SHOULD NOT BE POPULATED." at 144.991,-8.077 h0.6
  text ".VariantName" at 118.473,-11.024 h0.6
  text "ASSEMBLY VARIANT:" at 144.864,-11.024 h0.6
  text ".VersionControl_RevNumber" at 16.302,-16.667 h0.6
  text "SVN REV:" at 29.154,-16.667 h0.6
  text ".PCB_Rev" at 43.035,-16.667 h0.6
  text "REV:" at 50.439,-16.667 h0.6
  text ".PRJ_Number" at 71.89,-16.667 h0.6
  text "BOARD #:" at 85.745,-16.667 h0.6
  text "PCB VIEWED FROM BOTTOM SIDE" at 148.648,-16.667 h0.6
  text ".TID" at 71.89,-21.831 h0.6
  text "TID #:" at 85.745,-21.831 h0.6
  text "TEXAS INSTRUMENTS" at 12.974,-27.047 h0.6
  text ".Print_Time" at 45.093,-27.047 h0.6
  text ".Print_Date" at 63.609,-27.047 h0.6
  text "GENERATED    :" at 85.694,-27.047 h0.6
  text ".plot_File_Name" at 128.189,-27.047 h0.6
  text "PLOT NAME =" at 148.648,-27.047 h0.6
M9 Title Sheet:
  drawing of 57 lines, arcs and shapes, not listed
  text "1" at 8.792,204.127 h1.78
  text "2" at 72.182,204.127 h1.78
  text "3" at 135.411,204.127 h1.78
  text "4" at 199.08,204.127 h1.78
  text "5" at 262.555,204.127 h1.78
  text "6" at 326.182,204.127 h1.78
  text "A" at -20.579,175.095 h1.78
  text "A" at 355.341,175.095 h1.78
  text "B" at -20.579,114.643 h1.78
  text "B" at 355.341,114.643 h1.78
  text "C" at -20.579,54.318 h1.78
  text "C" at 355.341,54.318 h1.78
  text "PROJECT TITLE:" at 278.125,7.048 h1.14
  text ".PRJ_Title" at 279.395,3.662 h1.78
  text "DESIGNED FOR:" at 278.125,-0.597 h1.14
  text ".PRJ_Customer" at 279.395,-4.153 h1.78
  text "D" at -20.579,-5.88 h1.78
  text "D" at 355.341,-5.88 h1.78
  text "FILE NAME:" at 278.125,-8.217 h1.14
  text ".PCB_File_Name_No_Path" at 279.395,-11.265 h1.78
  text "Texas Instruments (TI) and/or its licensors do not warrant the accuracy or completeness of this specification" at 151.9,-15.376 h1.14
  text "ENGINEER:" at 278.125,-15.583 h1.14
  text "LAYOUT BY:" at 316.352,-15.583 h1.14
  text "or any information contained therein. TI and/or its licensors do not warrant that this design will meet" at 150.757,-18.237 h1.14
  text ".PRJ_Engineer" at 279.395,-19.52 h1.78
  text ".PCB_Layout" at 317.635,-19.52 h1.78
  text "the specifications, will be suitable for your application or fit for any particular purpose, or will operate in" at 150.757,-21.099 h1.14
  text ".Layer_Name" at 4.656,-21.806 h0.6
  text "ALTIUM DESIGNER VERSION:" at 316.352,-23.457 h1.14
  text "an implementation. TI and/or its licensors do not warrant that the design is production worthy. You should" at 150.757,-23.961 h1.14
  text "completely validate and test your design implementation to confirm the system functionality for your application." at 151.9,-26.822 h1.14
  text ".print_Scale" at 279.395,-26.843 h1.78
  text ".Application_BuildNumber" at 317.635,-26.843 h1.78
  text "1" at 8.792,-32.093 h1.78
  text "2" at 72.182,-32.093 h1.78
  text "3" at 135.411,-32.093 h1.78
  text "4" at 199.08,-32.093 h1.78
  text "5" at 262.555,-32.093 h1.78
  text "6" at 326.182,-32.093 h1.78
M10 Fab Notes:
  drawing of 224 lines, arcs and shapes, not listed
  text "DESIGN INFORMATION" at 304.503,161.447 h0.6
  text "MIN. TRACK WIDTH:" at 288.131,158.091 h0.6
  text "8" at 315.976,158.091 h0.6
  text "MIL" at 319.907,158.091 h0.6
  text "7.874" at 311.75,155 h0.6
  text "MIN. CLEARANCE:" at 288.131,154.938 h0.6
  text "MIL" at 319.907,154.938 h0.6
  text "MIN. VIA PAD SIZE:" at 288.131,151.785 h0.6
  text "24" at 315.214,151.785 h0.6
  text "MIL" at 319.907,151.785 h0.6
  text "0.05mm (2MIL)" at 305.784,148.486 h0.6
  text "MINIMUM ANNULAR RING" at 279.769,148.277 h0.6
  text "EXTERNAL" at 323.768,148.277 h0.6
  text "PER" at 284.849,145.48 h0.6
  text "IPC-D-275 CLASS 2 LEVEL C" at 290.437,145.48 h0.6
  text "MIL, HOLES" at 328.238,142.928 h0.6
  text "+/-" at 318.27,142.709 h0.6
  text "+/-" at 339.961,142.709 h0.6
  text "REGISTRATION TOLERANCES:" at 279.769,142.682 h0.6
  text "METAL" at 310.243,142.682 h0.6
  text "5" at 324.879,142.683 h0.6
  text "3" at 346.037,142.683 h0.6
  text "MIL" at 348.99,142.682 h0.6
  text "HOLE SIZE TOLERANCE (UNLESS OTHERWISE SPECIFIED):" at 279.769,140.185 h0.6
  text "+/-" at 339.961,140.112 h0.6
  text "3" at 346.037,140.085 h0.6
  text "MIL" at 348.99,140.085 h0.6
  text "MATERIAL:" at 277.87,136.589 h0.6
  text "FR-4 High Tg" at 302.926,133.324 h0.6
  text "X" at 299.257,133.122 h0.6
  text "FR-4" at 288.563,133.007 h0.6
  text "OTHER" at 326.358,133.007 h0.6
  text "62 MIL (1.6mm) +/-10%" at 296.694,129.374 h0.6
  text "X" at 293.643,129.312 h0.6
  text "THICKNESS:" at 279.769,129.165 h0.6
  text "OTHER" at 329.33,129.165 h0.6
  text "TOLERANCE:" at 279.769,125.652 h0.6
  text "X" at 301.314,125.652 h0.6
  text "ANSI IPC-6012 TYPE 3 CLASS 2" at 305.836,125.652 h0.6
  text "OTHER +/-" at 305.835,121.989 h0.6
  text "BOW & TWIST:" at 279.769,118.302 h0.6
  text "X" at 301.314,118.302 h0.6
  text "ANSI IPC-6012 TYPE 3 CLASS 2" at 305.836,118.302 h0.6
  text "OTHER +/-" at 305.835,114.576 h0.6
  text "DRILLING:" at 277.87,111.258 h0.6
  text "NC_DRILL FILES" at 322.599,108.586 h0.6
  text "REFERENCE:" at 279.769,108.486 h0.6
  text "X" at 296.463,108.484 h0.6
  text "AS SHOWN" at 300.984,108.486 h0.6
  text "X" at 319.348,108.486 h0.6
  text "OTHER" at 330.168,104.873 h0.6
  text "PTH COPPER THICKNESS:" at 279.761,104.783 h0.6
  text "X" at 308.697,104.783 h0.6
  text "20-30 um" at 311.948,104.783 h0.6
  text "BOARD FINISH:" at 277.87,101.034 h0.6
  text "SILKSCREEN:" at 281.812,98.237 h0.6
  text "X" at 306.14,98.237 h0.6
  text "TOP" at 309.112,98.237 h0.6
  text "X" at 319.094,98.237 h0.6
  text "BOTTOM" at 322.091,98.237 h0.6
  text "SILKSCREEN COLOR:" at 281.812,94.295 h0.6
  text "X" at 306.115,94.295 h0.6
  text "WHITE" at 309.112,94.295 h0.6
  text "OTHER" at 322.091,94.295 h0.6
  text "X" at 309.442,90.652 h0.6
  text "GREEN" at 312.439,90.652 h0.6
  text "OTHER" at 328.136,90.652 h0.6
  text "SOLDER RESIST COLOR:" at 281.812,90.477 h0.6
  text "X" at 309.442,86.734 h0.6
  text "MATTE" at 312.439,86.734 h0.6
  text "SEMI-GLOSS" at 328.125,86.717 h0.6
  text "IMMERSION GOLD (ENIG)" at 304.819,82.345 h0.6
  text "ENEPIG" at 338.793,82.162 h0.6
  text "SURFACE FINISH:" at 277.87,82.136 h0.6
  text "X" at 300.298,82.136 h0.6
  text "IMM. TIN/SILVER OR EQUIV" at 286.24,78.649 h0.6
  text "OTHER" at 322.599,78.549 h0.6
  text "ARRAY/PANEL:" at 277.87,74.602 h0.6
  text "CUT AND TRIM PER M1 BOARD OUTLINE" at 304.819,74.393 h0.6
  text "N.C. ROUTE" at 304.819,70.94 h0.6
  text "X" at 322.295,70.94 h0.6
  text "V. SCORE" at 326.816,70.94 h0.6
  text "CERTIFICATION:" at 277.87,67.66 h0.6
  text "MATERIALS AND WORKMANSHIP FOR ALL PCBS" at 296.285,67.66 h0.6
  text "TO MEET OR EXCEED THE REQUIREMENTS OF:" at 296.285,65.271 h0.6
  text "X" at 287.078,62.003 h0.6
  text "ANSI IPC-A-600F CLASS ->" at 290.329,62.003 h0.6
  text "X" at 332.188,62.003 h0.6
  text "2" at 334.982,62.003 h0.6
  text "1" at 326.981,61.965 h0.6
  text "3" at 343.973,61.965 h0.6
  text "X" at 307.702,58.252 h0.6
  text "RoHS" at 310.953,58.252 h0.6
  text "OTHER" at 327.321,58.252 h0.6
  text "PER ORDER" at 337.407,58.252 h0.6
  text "ALL BOARDS MUST MEET OR EXCEED UL94-V0 REQUIREMENTS." at 278.569,54.345 h0.6
  text "PCB MUST BEAR THE UL94V-0 UL REGISTERED MATERIAL ID NUMBER" at 278.569,51.397 h0.6
  text "ADDITIONAL REQUIREMENTS:" at 277.87,47.094 h0.6
  text "MICROSECTION:" at 279.769,44.373 h0.6
  text "YES" at 302.775,44.373 h0.6
  text "REQUIRED" at 324.657,40.707 h0.6
  text "BARE BOARD ELEC. TEST:" at 279.769,40.634 h0.6
  text "NONE" at 312.935,40.634 h0.6
  text "X" at 321.66,40.634 h0.6
  text "PER ORDER" at 339.693,40.634 h0.6
  text "XX MIL VIAS REQUIRE NON-CONDUCTIVE FILL AND PLANARIZE" at 284.04,35.428 h1.5
  text "XX MIL VIAS REQUIRE CONDUCTIVE FILL AND PLANARIZE" at 284.243,32.787 h0.6
  text "OUTER XX MIL TRACES REQUIRE 50 OHM SINGLE-ENDED IMPEDANCE" at 284.218,28.637 h1.47
  text "LAYER 2 & 3 (INNER LAYERS) XX MIL WIDE, XX MIL SPACE / TRACES REQUIRE 100 OHM DIFFERENTIAL IMPEDANCE" at 284.015,22.65 h0.6
  text ".Layer_Name" at 4.656,-21.806 h0.6
  text "The side of PCB should be metallized" at 49.678,-32.346 h1.85
M11 Gerber Information:
  lines w0.254: -17.417,-23.626 150.223,-23.626 ; -17.417,-18.462 150.274,-18.462 ; -17.417,-13.297 -17.417,-28.791 84.31,-28.791 150.274,-28.791 150.274,-13.297 -17.404,-13.297 -17.404,-28.791 22.614,-28.791 ; 45.194,-28.791 45.194,-13.297 ; 77.376,-18.462 77.376,-13.297 ; 98.712,-18.462 98.712,-13.297 ; 114.511,-28.956 114.511,-23.804
  text "ALL ARTWORK VIEWED FROM TOP SIDE" at -15.804,-16.654 h0.6
  text "BOARD #:" at 47.099,-16.654 h0.6
  text ".PRJ_Number" at 60.955,-16.654 h0.6
  text "REV:" at 82.405,-16.654 h0.6
  text ".PCB_Rev" at 89.809,-16.654 h0.6
  text "SVN REV:" at 103.69,-16.654 h0.6
  text ".VersionControl_RevNumber" at 116.543,-16.654 h0.6
  text "LAYER NAME =" at -15.804,-21.806 h0.6
  text "TID #:" at 47.099,-21.819 h0.6
  text ".TID" at 60.955,-21.819 h0.6
  text "PLOT NAME =" at -15.804,-27.034 h0.6
  text ".plot_File_Name" at 4.656,-27.034 h0.6
  text "GENERATED    :" at 47.15,-27.034 h0.6
  text ".Print_Date" at 69.235,-27.034 h0.6
  text ".Print_Time" at 87.752,-27.034 h0.6
  text "TEXAS INSTRUMENTS" at 119.87,-27.034 h0.6
M12 Stackup:
  text ".Layer_Name" at 4.656,-21.806 h0.6
M13 Component Bodies Top:
  text ".Layer_Name" at 4.656,-21.806 h0.6
M14 Component Bodies Bottom:
  text ".Layer_Name" at 4.656,-21.806 h0.6
M15 Courtyards Top:
  text ".Layer_Name" at 4.656,-21.806 h0.6
M16 Courtyards Bottom:
  text ".Layer_Name" at 4.656,-21.806 h0.6
Drill Drawing:
  text ".Layer_Name" at 4.656,-21.806 h0.6
M17 Embedded Cavity:
  text ".Layer_Name" at 4.656,-21.806 h0.6
M18 Embedded Assembly:
  text ".Layer_Name" at 4.656,-21.806 h0.6
M19 Embedded Keepout:
  text ".Layer_Name" at 4.656,-21.806 h0.6

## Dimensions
96,5 to 101.746,67.935 on M2 Board Dimensions
96,5 to 101.746,67.935 on M2 Board Dimensions
96,35 to -8.263,67.94 on M2 Board Dimensions
96,35 to -8.263,67.94 on M2 Board Dimensions
9,35.35 to -8.268,0.003 on M2 Board Dimensions
8.8,35 to -8.268,0.003 on M2 Board Dimensions
10.75,5 to 7,0 on M2 Board Dimensions
9,4.2 to 7,0 on M2 Board Dimensions
9,5 to 11.782,2.218 on M2 Board Dimensions
-8.268,0.003 to -8.263,67.94 on M2 Board Dimensions
7,0 to -8.268,0.003 on M2 Board Dimensions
